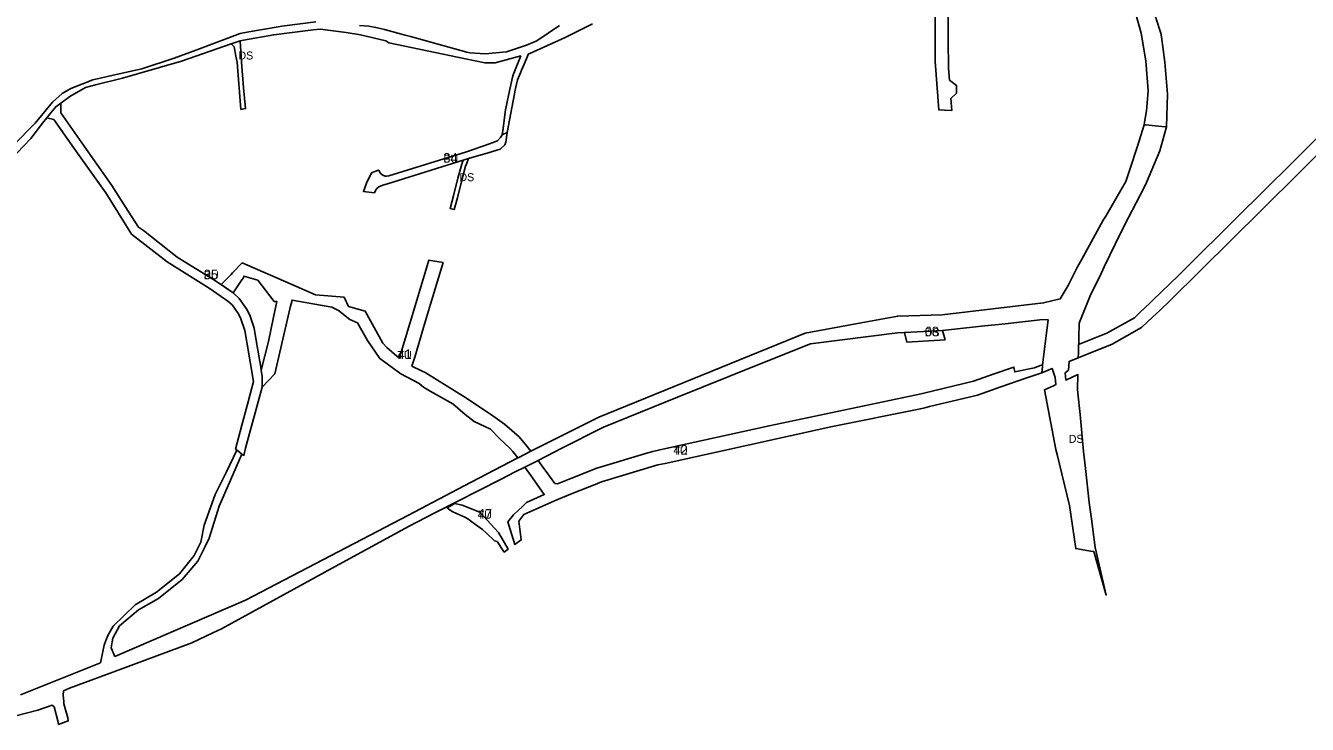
# Model space of a CAD drawing. Extents: x -535435 to -532834, y -1165802 to -1163866.
# Drawn here: x -534910 to -534109, y -1165571 to -1165135 of the extents above; entities that cross this region are included whole.
import ezdxf

# ---------------------------------------------------------------- set-up
doc = ezdxf.new("R2010")
doc.units = 0
for name, color, linetype in [('90320013', 7, 'Continuous'), ('90320023', 7, 'Continuous'), ('90380023', 7, 'Continuous'), ('90450013', 7, 'Continuous'), ('90450023', 7, 'Continuous'), ('ID_navrh', 7, 'Continuous')]:
    doc.layers.add(name, color=color, linetype=linetype)

msp = doc.modelspace()

# ---------------------------------------------------------------- linework, layer by layer
at = {"layer": '90320013'}
for points in [[(-534779.24, -1165147.77), (-534781.076, -1165145.96), (-534775.49, -1165144.03), (-534775.25, -1165147.5), (-534775.05, -1165150.33), (-534774.83, -1165153.47), (-534774.56, -1165157.32), (-534773.45, -1165173.38), (-534772.09, -1165186.32), (-534774.981, -1165186.877), (-534777.364, -1165157.303), (-534778.072, -1165153.706)], [(-534636.153, -1165218.674), (-534632.69, -1165217.6), (-534633.92, -1165220.53), (-534634.63, -1165222.23), (-534636.98, -1165231.14), (-534639.72, -1165242.1), (-534641.82, -1165249.4), (-534644.287, -1165248.754), (-534642.21, -1165240.82), (-534639.56, -1165229.81), (-534636.93, -1165221.04)]]:
    msp.add_lwpolyline(points, close=True, dxfattribs=at)
msp.add_lwpolyline([(-534912.68, -1165552.42), (-534877.24, -1165538.36), (-534862.8, -1165532.4), (-534861.32, -1165525.37), (-534860.51, -1165521.43), (-534860.3, -1165520.88), (-534858.97, -1165517.45), (-534858.15, -1165515.35), (-534854.91, -1165509.61), (-534841.13, -1165496.3), (-534827.72, -1165488.42), (-534813.3, -1165476.94), (-534804.19, -1165465.36), (-534800.02, -1165457.14), (-534797.86, -1165446.44), (-534791.04, -1165427.36), (-534783.92, -1165413.27), (-534777.48, -1165399.64), (-534777.14, -1165399.85), (-534774.44, -1165402.06), (-534788.69, -1165434.63), (-534794.8, -1165454.57), (-534797.58, -1165460.25), (-534801.92, -1165469.07), (-534811.76, -1165480.33), (-534826.42, -1165492.24), (-534839.06, -1165499.27), (-534850.87, -1165509.4), (-534854.95, -1165517.06), (-534855.37, -1165519.3), (-534856.09, -1165523.12), (-534853.75, -1165528.43), (-534772.12, -1165493.42), (-534670.299, -1165440.18), (-534635.941, -1165422.215), (-534601.98, -1165404.458), (-534601.41, -1165404.16), (-534593.742, -1165400.311), (-534551.38, -1165379.05), (-534422.4, -1165326.53), (-534387.514, -1165320.16), (-534364.57, -1165315.97), (-534336.76, -1165315.12), (-534273.43, -1165307.68), (-534263.07, -1165305.2), (-534258.18, -1165296.74), (-534255.45, -1165291.38), (-534252.19, -1165285.28), (-534249.84, -1165280.89), (-534236.16, -1165256.09), (-534234.65, -1165253.49), (-534222.12, -1165231.81), (-534219.65, -1165224.42), (-534214.76, -1165209.81), (-534210.61, -1165196.44), (-534209.353, -1165196.559), (-534203.697, -1165197.093), (-534199.602, -1165197.575), (-534196.74, -1165197.75), (-534200.78, -1165212.83), (-534209.06, -1165232.51), (-534210.89, -1165236.07), (-534220.39, -1165254.46), (-534225.18, -1165263.79), (-534235.49, -1165285.14), (-534237.36, -1165289.01), (-534240.88, -1165296.25), (-534241.33, -1165297.17), (-534244.31, -1165303.28), (-534251.27, -1165320.44), (-534251.69, -1165338.72), (-534251.77, -1165341.96), (-534257.49, -1165344.29), (-534257.97, -1165349.66), (-534259.96, -1165351.32), (-534259.48, -1165355.88), (-534252.01, -1165352.47), (-534252.23, -1165361.54), (-534251.99, -1165363.99), (-534250.69, -1165377.47), (-534248.48, -1165400.41), (-534247.31, -1165411.07), (-534244.98, -1165432.27), (-534243.4, -1165444.03), (-534242.7, -1165449.22), (-534241.22, -1165460.36), (-534234.3, -1165490.14), (-534242.12, -1165462.96), (-534244.14, -1165462.64), (-534249.66, -1165461.74), (-534253.34, -1165461.15), (-534257.19, -1165434.29), (-534262.04, -1165414.36), (-534264.94, -1165402.42), (-534265.72, -1165399.2), (-534272.9, -1165362.02), (-534267.32, -1165359.47), (-534265.74, -1165358.75), (-534266.24, -1165354.33), (-534268.13, -1165348.62), (-534274.64, -1165351.27), (-534274.2, -1165347.69), (-534274.043, -1165346.403), (-534270.61, -1165318.24), (-534273.89, -1165318.16), (-534297.487, -1165320.705), (-534312.18, -1165322.29), (-534336.67, -1165324.94), (-534360.45, -1165326.25), (-534364.65, -1165326.48), (-534419.17, -1165333.25), (-534454.003, -1165347.255), (-534502.24, -1165366.65), (-534548.51, -1165385.26), (-534574.828, -1165398.663), (-534589.332, -1165406.049), (-534597.581, -1165410.25), (-534603.53, -1165413.28), (-534612.41, -1165417.8), (-534653.44, -1165438.69), (-534670.22, -1165447.23), (-534722.56, -1165475.88), (-534787.1, -1165511.18), (-534792.57, -1165513.75), (-534805.71, -1165519.94), (-534849.32, -1165536.17), (-534882.03, -1165548.34), (-534885.76, -1165550.05), (-534886.11, -1165552.64), (-534885.69, -1165556.54), (-534885.55, -1165558), (-534883.19, -1165566.76), (-534882.85, -1165568.74), (-534888.88, -1165570.88), (-534889.42, -1165568.74), (-534891.75, -1165560.02), (-534893.04, -1165558.98), (-534901.88, -1165561.94), (-534915.56, -1165565.61)], dxfattribs=at)
at = {"layer": '90320023'}
msp.add_lwpolyline([(-534335.046, -1165330.86), (-534358.826, -1165332.17), (-534360.45, -1165326.25), (-534336.67, -1165324.94)], close=True, dxfattribs=at)
at = {"layer": '90380023'}
msp.add_lwpolyline([(-534066.72, -1165179.82), (-534136.8, -1165249.37), (-534194.29, -1165306.12), (-534200.89, -1165312.54), (-534205.31, -1165316.61), (-534212.27, -1165323.02), (-534230.69, -1165333.38), (-534251.77, -1165341.96), (-534251.69, -1165338.72), (-534251.577, -1165333.784), (-534233.955, -1165326.611), (-534216.742, -1165316.93), (-534213.981, -1165314.335), (-534213.437, -1165313.824), (-534206.827, -1165307.611), (-534205.1, -1165305.987), (-534189.229, -1165290.586), (-534149.077, -1165250.937), (-534139.471, -1165241.41), (-534114.175, -1165216.322), (-534101.588, -1165203.839)], dxfattribs=at)
for points in [[(-534619.01, -1165386.65), (-534622.61, -1165384.94), (-534629.25, -1165381.75), (-534634.894, -1165377.362), (-534642.55, -1165370.754), (-534656.806, -1165362.855), (-534660.93, -1165360.38), (-534663.67, -1165357.97), (-534675.04, -1165351.98), (-534688.17, -1165342.38), (-534695.88, -1165331.28), (-534702.167, -1165320.064), (-534706.875, -1165318.091), (-534714.037, -1165312.461), (-534718.125, -1165310.44), (-534743.052, -1165305.979), (-534744.129, -1165310.569), (-534750.684, -1165338.491), (-534753.851, -1165351.984), (-534761.79, -1165360.41), (-534761.628, -1165353.688), (-534762.293, -1165349.741), (-534757.69, -1165331.84), (-534754.687, -1165316.58), (-534752.459, -1165306.87), (-534754.18, -1165306.73), (-534764.53, -1165293.41), (-534773.21, -1165290.92), (-534773.48, -1165292.09), (-534774.33, -1165293.32), (-534779.49, -1165300.88), (-534779.821, -1165301.364), (-534787.427, -1165296.268), (-534781.185, -1165289.896), (-534780.217, -1165288.907), (-534774.177, -1165282.743), (-534743.59, -1165295.91), (-534728.29, -1165302.64), (-534710.5, -1165304.17), (-534707.83, -1165309.96), (-534697.266, -1165312.904), (-534686.218, -1165332.95), (-534683.831, -1165335.456), (-534676.018, -1165342.285), (-534674.897, -1165338.553), (-534669.517, -1165320.647), (-534664.905, -1165305.299), (-534657.628, -1165281.081), (-534652.53, -1165281.94), (-534648.661, -1165282.513), (-534656.466, -1165308.487), (-534660.844, -1165323.061), (-534666.386, -1165341.503), (-534668.097, -1165347.197), (-534662.084, -1165350.114), (-534659.903, -1165351.067), (-534633.99, -1165367.14), (-534617.669, -1165378.227), (-534610.247, -1165383.446), (-534601.042, -1165391.405), (-534598.221, -1165394.846), (-534597.026, -1165396.305), (-534593.742, -1165400.311), (-534601.41, -1165404.16), (-534601.98, -1165404.458), (-534605.192, -1165400.539), (-534607.004, -1165398.328), (-534613.509, -1165392.332)], [(-534567.01, -1165426.39), (-534577.5, -1165430.58), (-534598.29, -1165439.76), (-534601.363, -1165444.1), (-534599.87, -1165455.71), (-534603.882, -1165458.535), (-534607.549, -1165446.401), (-534608.122, -1165444.506), (-534604.649, -1165440.099), (-534601.568, -1165437.166), (-534599.518, -1165435.213), (-534596.584, -1165432.419), (-534585.468, -1165427.37), (-534592.444, -1165417.51), (-534593.887, -1165415.471), (-534597.581, -1165410.25), (-534589.332, -1165406.049), (-534585.708, -1165411.053), (-534584.327, -1165412.961), (-534578.843, -1165420.532), (-534577.132, -1165420.742), (-534568.837, -1165417.43), (-534552.702, -1165410.995), (-534520.704, -1165401.395), (-534517.583, -1165400.459), (-534513.151, -1165399.411), (-534444.988, -1165384.388), (-534349.958, -1165364.505), (-534348.18, -1165364.088), (-534317.266, -1165356.626), (-534304.229, -1165352.074), (-534292.023, -1165347.813), (-534291.425, -1165350.782), (-534279.12, -1165348.18), (-534275.59, -1165346.89), (-534274.043, -1165346.403), (-534274.2, -1165347.69), (-534274.64, -1165351.27), (-534284.53, -1165354.73), (-534300.23, -1165360.21), (-534314.72, -1165365.27), (-534327.1, -1165368.26), (-534344.67, -1165372.49), (-534347.57, -1165373.21), (-534350.42, -1165373.76), (-534406.37, -1165385.09), (-534509.97, -1165407.93), (-534512.18, -1165408.41), (-534514.4, -1165408.9), (-534549.73, -1165419.5), (-534554.75, -1165421.51)], [(-534636.67, -1165433.924), (-534625.805, -1165438.391), (-534614.062, -1165451.061), (-534607.908, -1165461.42), (-534610.461, -1165463.267), (-534614.92, -1165456.72), (-534616.51, -1165456.28), (-534621.78, -1165451.3), (-534624.12, -1165449.21), (-534629.91, -1165445), (-534631.5, -1165443.83), (-534633.13, -1165442.51), (-534635.1, -1165441.55), (-534642.65, -1165438.14), (-534644.3, -1165437.19), (-534646.155, -1165435.684), (-534641.319, -1165433.008)]]:
    msp.add_lwpolyline(points, close=True, dxfattribs=at)
at = {"layer": '90450013'}
for points in [[(-534203.92, -1165127.62), (-534201, -1165136.72), (-534200.14, -1165139.35), (-534199.83, -1165141.58), (-534197.6, -1165157.43), (-534196.09, -1165177.34), (-534196.74, -1165197.75), (-534199.602, -1165197.575), (-534203.697, -1165197.093), (-534209.353, -1165196.559), (-534210.61, -1165196.44), (-534210.334, -1165194.82), (-534209.14, -1165187.8), (-534208.19, -1165175.29), (-534209.51, -1165156.58), (-534212.54, -1165139.35), (-534217.22, -1165122.23)], [(-534917.33, -1165209.45), (-534903.6, -1165195.4), (-534892.73, -1165182.38), (-534886.69, -1165177.01), (-534881.29, -1165173.85), (-534867.51, -1165168.45), (-534851.12, -1165164.76), (-534836.95, -1165161.52), (-534816.66, -1165154.98), (-534802.57, -1165149.67), (-534775.57, -1165139.44), (-534770.12, -1165138.51), (-534751.63, -1165135.33), (-534749.51, -1165134.97), (-534728.232, -1165132.152)], [(-534555.22, -1165133.48), (-534572.34, -1165142), (-534594.43, -1165152.01), (-534595.356, -1165152.25), (-534598.66, -1165160.11), (-534599.6, -1165162.33), (-534600.32, -1165164.01), (-534602.14, -1165168.33), (-534603.51, -1165173.76), (-534608.72, -1165201.29), (-534611.73, -1165202.83), (-534611.2, -1165198.9), (-534610.1, -1165190.23), (-534609.72, -1165187.18), (-534607.79, -1165178.29), (-534605.25, -1165166.64), (-534604.96, -1165165.29), (-534600.19, -1165153.5), (-534616.15, -1165157.87), (-534622.58, -1165157.86), (-534634.671, -1165155.336), (-534682.61, -1165145.33), (-534684.51, -1165144.15), (-534700.3, -1165140.27), (-534709.27, -1165138.78), (-534725.42, -1165136.87), (-534729.95, -1165137.1), (-534754.46, -1165140.25), (-534773.4, -1165143.64), (-534775.49, -1165144.03), (-534781.076, -1165145.96), (-534812.16, -1165156.7), (-534839.59, -1165164.67), (-534848.93, -1165167.39), (-534865.77, -1165171.59), (-534872.13, -1165173.18), (-534881.84, -1165178.84), (-534887.577, -1165182.941), (-534890.71, -1165185.18), (-534893.87, -1165188.98), (-534896.255, -1165192.039), (-534899, -1165195.56), (-534906.33, -1165204.96), (-534915.11, -1165214.3)], [(-534700.81, -1165134.426), (-534695.14, -1165134.964), (-534690.72, -1165135.63), (-534685.34, -1165137.05), (-534672.46, -1165140.44), (-534669.005, -1165141.449), (-534637.485, -1165150.025), (-534633.914, -1165151.109), (-534631.908, -1165151.48), (-534622.288, -1165152.228), (-534608.982, -1165150.826), (-534596.597, -1165146.721), (-534590.09, -1165143.97), (-534575.87, -1165134.421)]]:
    msp.add_lwpolyline(points, dxfattribs=at)
at = {"layer": '90450023'}
msp.add_lwpolyline([(-534333.054, -1165125.224), (-534333.121, -1165143.491), (-534332.816, -1165161.242), (-534332.242, -1165168.559), (-534327.902, -1165171.873), (-534327.9, -1165174.273), (-534327.898, -1165176.673), (-534331.335, -1165180.116), (-534330.752, -1165187.542), (-534335.39, -1165187.36), (-534338.8, -1165187.24), (-534341.17, -1165157.05), (-534340.945, -1165094.96)], dxfattribs=at)
for points in [[(-534887.604, -1165189.065), (-534874.302, -1165207.836), (-534855.587, -1165234.294), (-534845.399, -1165250.417), (-534839.01, -1165260.41), (-534835.81, -1165262.59), (-534814.861, -1165279.073), (-534790.881, -1165293.953), (-534779.821, -1165301.364), (-534776.083, -1165304.947), (-534771.411, -1165311.31), (-534769.399, -1165315.334), (-534766.72, -1165323.467), (-534765.202, -1165332.461), (-534762.608, -1165347.87), (-534762.293, -1165349.741), (-534761.628, -1165353.688), (-534761.79, -1165360.41), (-534772.095, -1165398.401), (-534773.095, -1165402.961), (-534774.44, -1165402.06), (-534777.14, -1165399.85), (-534777.48, -1165399.64), (-534778.381, -1165399.056), (-534774.348, -1165383.985), (-534770.467, -1165369.485), (-534767.05, -1165356.72), (-534771.118, -1165333.459), (-534772.56, -1165324.913), (-534774.961, -1165317.626), (-534776.549, -1165314.45), (-534780.557, -1165308.993), (-534783.149, -1165306.655), (-534794.119, -1165299.007), (-534799.913, -1165295.461), (-534820.981, -1165282.126), (-534843.373, -1165264.698), (-534859.493, -1165238.974), (-534879.198, -1165211.303), (-534891.914, -1165193.167), (-534896.255, -1165192.039), (-534893.87, -1165188.98), (-534890.71, -1165185.18), (-534887.577, -1165182.941)], [(-534619.672, -1165208.32), (-534614.687, -1165206.463), (-534612.857, -1165204.39), (-534611.73, -1165202.83), (-534608.72, -1165201.29), (-534609.411, -1165207.236), (-534610.136, -1165208.971), (-534613.071, -1165211.633), (-534620.573, -1165213.915), (-534632.69, -1165217.6), (-534636.153, -1165218.674), (-534683.404, -1165233.352), (-534685.716, -1165234.065), (-534687.313, -1165234.607), (-534688.724, -1165235.276), (-534689.975, -1165236.279), (-534690.956, -1165237.548), (-534691.61, -1165239), (-534698.451, -1165238.101), (-534696.454, -1165232.948), (-534693.462, -1165226.393), (-534689.62, -1165225.087), (-534688.823, -1165224.816), (-534688.098, -1165226.32), (-534687.28, -1165227.291), (-534687.132, -1165227.394), (-534686.326, -1165227.952), (-534684.957, -1165228.474), (-534683.941, -1165228.548), (-534682.53, -1165228.333), (-534634.06, -1165213.3)]]:
    msp.add_lwpolyline(points, close=True, dxfattribs=at)

# ---------------------------------------------------------------- texts
at = {"layer": '90320013'}
for rotation, p in [(0, (-534776.583, -1165155.7016)), (0.0000001, (-534638.4885, -1165231.7055)), (360, (-534257.7514, -1165395.1015))]:
    msp.add_text('DS', height=5, rotation=rotation, dxfattribs=at).set_placement(p)
at = {"layer": '90320023'}
msp.add_text('DS', height=5, rotation=359.9999999, dxfattribs=at).set_placement((-534347.748, -1165328.555))
at = {"layer": '90380023'}
for rotation, p in [(360, (-534677.2019, -1165342.7695)), (360, (-534504.7416, -1165402.469)), (0.0000001, (-534627.0315, -1165442.4899))]:
    msp.add_text('TU', height=5, rotation=rotation, dxfattribs=at).set_placement(p)
at = {"layer": '90450023'}
for rotation, p in [(0.0000001, (-534648.5092, -1165220.145)), (359.9999999, (-534798.1872, -1165292.951))]:
    msp.add_text('PU', height=5, rotation=rotation, dxfattribs=at).set_placement(p)
at = {"layer": 'ID_navrh'}
for s, rotation, p in [('34', 360, (-534648.5092, -1165220.145)), ('35', 0, (-534798.1872, -1165292.951)), ('68', 360, (-534347.748, -1165328.555)), ('47', 0, (-534627.0315, -1165442.4899))]:
    msp.add_text(s, height=6, rotation=rotation, dxfattribs=at).set_placement(p)
for s, p in [('41', (-534677.2019, -1165342.7695)), ('42', (-534504.7416, -1165402.469))]:
    msp.add_text(s, height=6, dxfattribs=at).set_placement(p)

doc.saveas('drawing.dxf')
